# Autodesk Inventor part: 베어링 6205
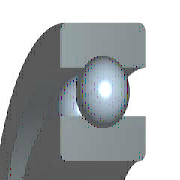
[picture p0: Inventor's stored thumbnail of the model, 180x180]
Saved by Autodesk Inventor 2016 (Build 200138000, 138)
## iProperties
Created: 2012-02
Part Number: 베어링 6205
Material: 강철, 연강
Description: 깊은 그루브 볼 베어링
Document SubType Name: Modeling
Standard: KS B 2023
Designer: mduedu
Standards Organization: KS
Language: ko-KR
Size Designation: 6205 - 25 x 52 x 15
Categories: <MemberInstance><Categories><Category DisplayName="샤프트 부품" InternalName="7f7aeb1f-a693-4053-b835-cee3144e0d98" Mnemonic="SHFT"><Category DisplayName="베어링" Inter
Density: 1 g/cm^3
Appearance: 노란색
IsCustomPart: 1
Author: mduedu
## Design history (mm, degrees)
sketch "스케치" dims "d0" = 7.02 (= -0.26 x WD + 0.26 x BD)
  geometry: L1 (3.99, 19.25)-(11.01, 19.25); L2 (7.5, 19.25)-(7.5, 15.74); L3 (7.5, 19.25)-(7.5, 22.76); L4 (4.892, 16.901)-(0, 16.901); L5 (0, 12.5)-(15, 12.5); L6 (4.892, 21.599)-(0, 21.599); L7 (0, 26)-(15, 26); L8 (15, 12.5)-(15, 16.901); L9 (10.108, 16.901)-(15, 16.901); L10 (10.108, 21.599)-(15, 21.599); L11 (15, 26)-(15, 21.599); L12 (-1.4, 0)-(8.4, 0) reference; L13 (0, -0.3)-(0, 5.3) reference
  constraints: 22 end point, 4 point on line, 2 collinear, 2 perpendicular, 2 symmetric about line, 1 midpoint, 1 parallel, 14 other
  dimensions: "d9" = 25 diameter of L5 L12 (= WD); "d11" = 52 diameter of L7 L12 (= BD); "d12" = 15 distance between parallel lines of L8 L13 (= KB); "d13" = 33.802 diameter of L9 L12 (= 0.326 x BD + 0.674 x WD)
revolve "본체" stored, may be unused: angle "d6" = 90 deg
revolve "볼" stored, may be unused: angle "d7" = 90 deg
pattern_circular "IDS_ARRAYBALL[SIMPL:T]" dims angle "d3" = 360 deg
body "Solid1"
fillet "모깎기1" dims "d1" = 1 (= KRS)
other parameters: "WD" = 25 [user parameter; used in 5 equation terms], "BD" = 52 [user parameter; used in 5 equation terms], "KB" = 15 [user parameter; used in 1 equation term], "KRS" = 1 [user parameter; used in 1 equation term], "d4" = 0, "d5" = 0, "d8" = 0, "d14" = 0, "d15" = 0, "BBA" = 0 [user parameter], "BC0" = 7800000 [user parameter], "BC" = 1.4e+07 [user parameter], "BR" = 26 (= 0.5 x BD) [user parameter], "WR" = 12.5 (= 0.5 x WD) [user parameter]
